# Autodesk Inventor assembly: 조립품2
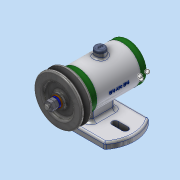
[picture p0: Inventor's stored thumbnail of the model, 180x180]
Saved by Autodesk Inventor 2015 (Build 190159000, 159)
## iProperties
Created: 2017-12
Part Number: 조립품2
Document SubType Name: Assembly
Designer: SCD-A03
Author: SCD-A03
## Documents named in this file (14)
- D:\1111\조립품2.iam
- D:\1111\부품2.ipt
- D:\1111\471208V1007\V벨트풀리.ipt
- D:\1111\471208V1007\고무캡.ipt
- D:\1111\471208V1007\너트 M 8.ipt
- D:\1111\471208V1007\뒤커버.ipt
- D:\1111\471208V1007\베어링 15 x 32 x 9.ipt
- D:\1111\471208V1007\볼트 M4 x 12.ipt
- D:\1111\471208V1007\스프링와셔 8.ipt
- D:\1111\471208V1007\앞커버.ipt
- D:\1111\471208V1007\오일 실 15 25 7.ipt
- D:\1111\471208V1007\와셔 8x17.ipt
- D:\1111\471208V1007\축.ipt
- D:\1111\471208V1007\키 3 x 3 x 12.ipt
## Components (2 placed, 2 different names)
1. V벨트풀리:1
2. 고무캡:1
